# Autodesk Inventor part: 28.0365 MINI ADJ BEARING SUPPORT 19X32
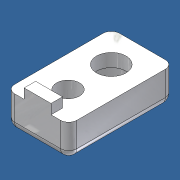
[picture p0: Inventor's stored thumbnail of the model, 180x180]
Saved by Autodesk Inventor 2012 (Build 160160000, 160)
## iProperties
Created: 2011-09
Part Number: 28.0365 MINI ADJ BEARING SUPPORT 19X32
Document SubType Name: Modeling
Designer: Administrator
Density: 2.71 g/cm^3
Mass: 11.6166 g
Surface Area: 25.5601 cm^2
Volume: 4.28657 cm^3
Material: Aluminum-6061
Description: MINI ADJ BEARING SUPPORT 45X45
Vendor: S
Author: Administrator
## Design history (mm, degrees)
feature "Base1"
sketch "Sketch1"
  geometry: L1 (0, -45)-(15.9, -45) reference; L2 (42.5, -42.5)-(42.501, -2.5) reference; L3 (29.5, -45)-(10.5, -45); L4 (10.5, -45)-(10.5, -13); L5 (10.5, -13)-(29.5, -13); L6 (29.5, -13)-(29.5, -45); L7 (29.5, -13)-(10.5, -13); L8 (10.5, -13)-(10.5, -45); L9 (10.5, -45)-(29.5, -45); L10 (29.5, -45)-(29.5, -13); L11 (10.5, -45)-(-40.639, -45); L12 (-40.639, -45)-(-40.639, 10.239); L13 (-40.639, 10.239)-(10.5, 10.239); L14 (10.5, 10.239)-(10.5, -45); L15 (10.5, 10.239)-(29.5, 10.239); L16 (29.5, 10.239)-(29.5, -13); L17 (29.5, -13)-(10.5, -13); L18 (10.5, -13)-(10.5, 10.239); L19 (29.5, 10.239)-(61.028, 10.239); L20 (61.028, 10.239)-(61.028, -64.268); L21 (61.028, -64.268)-(29.5, -64.268); L22 (29.5, -64.268)-(29.5, 10.239); 1 further point
  constraints: 40 end point, 10 parallel, 5 horizontal, 5 perpendicular
  dimensions: "d0" = 19 distance of L3.start L3.end; "d1" = 32 distance of L3.end L4.end; "d2" = 13 distance from line of L3.start L2; "d3" = 0 distance between parallel lines of L3 L1
extrude "Extrusion1" cut sketch "Sketch1" distance "d4" = 10; taper "d5" = 0 deg
fillet "Fillet1" dims "d6" = 2.5
body "Solid1"
